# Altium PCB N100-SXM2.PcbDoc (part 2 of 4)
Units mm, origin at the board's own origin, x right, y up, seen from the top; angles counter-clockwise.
Board outline 120 x 145 mm, 4 copper layers (Top Layer, GND, PWR, Bottom Layer), stack 0.603 mm thick; 267 components, 207 nets, 1440 pads, 915 vias.
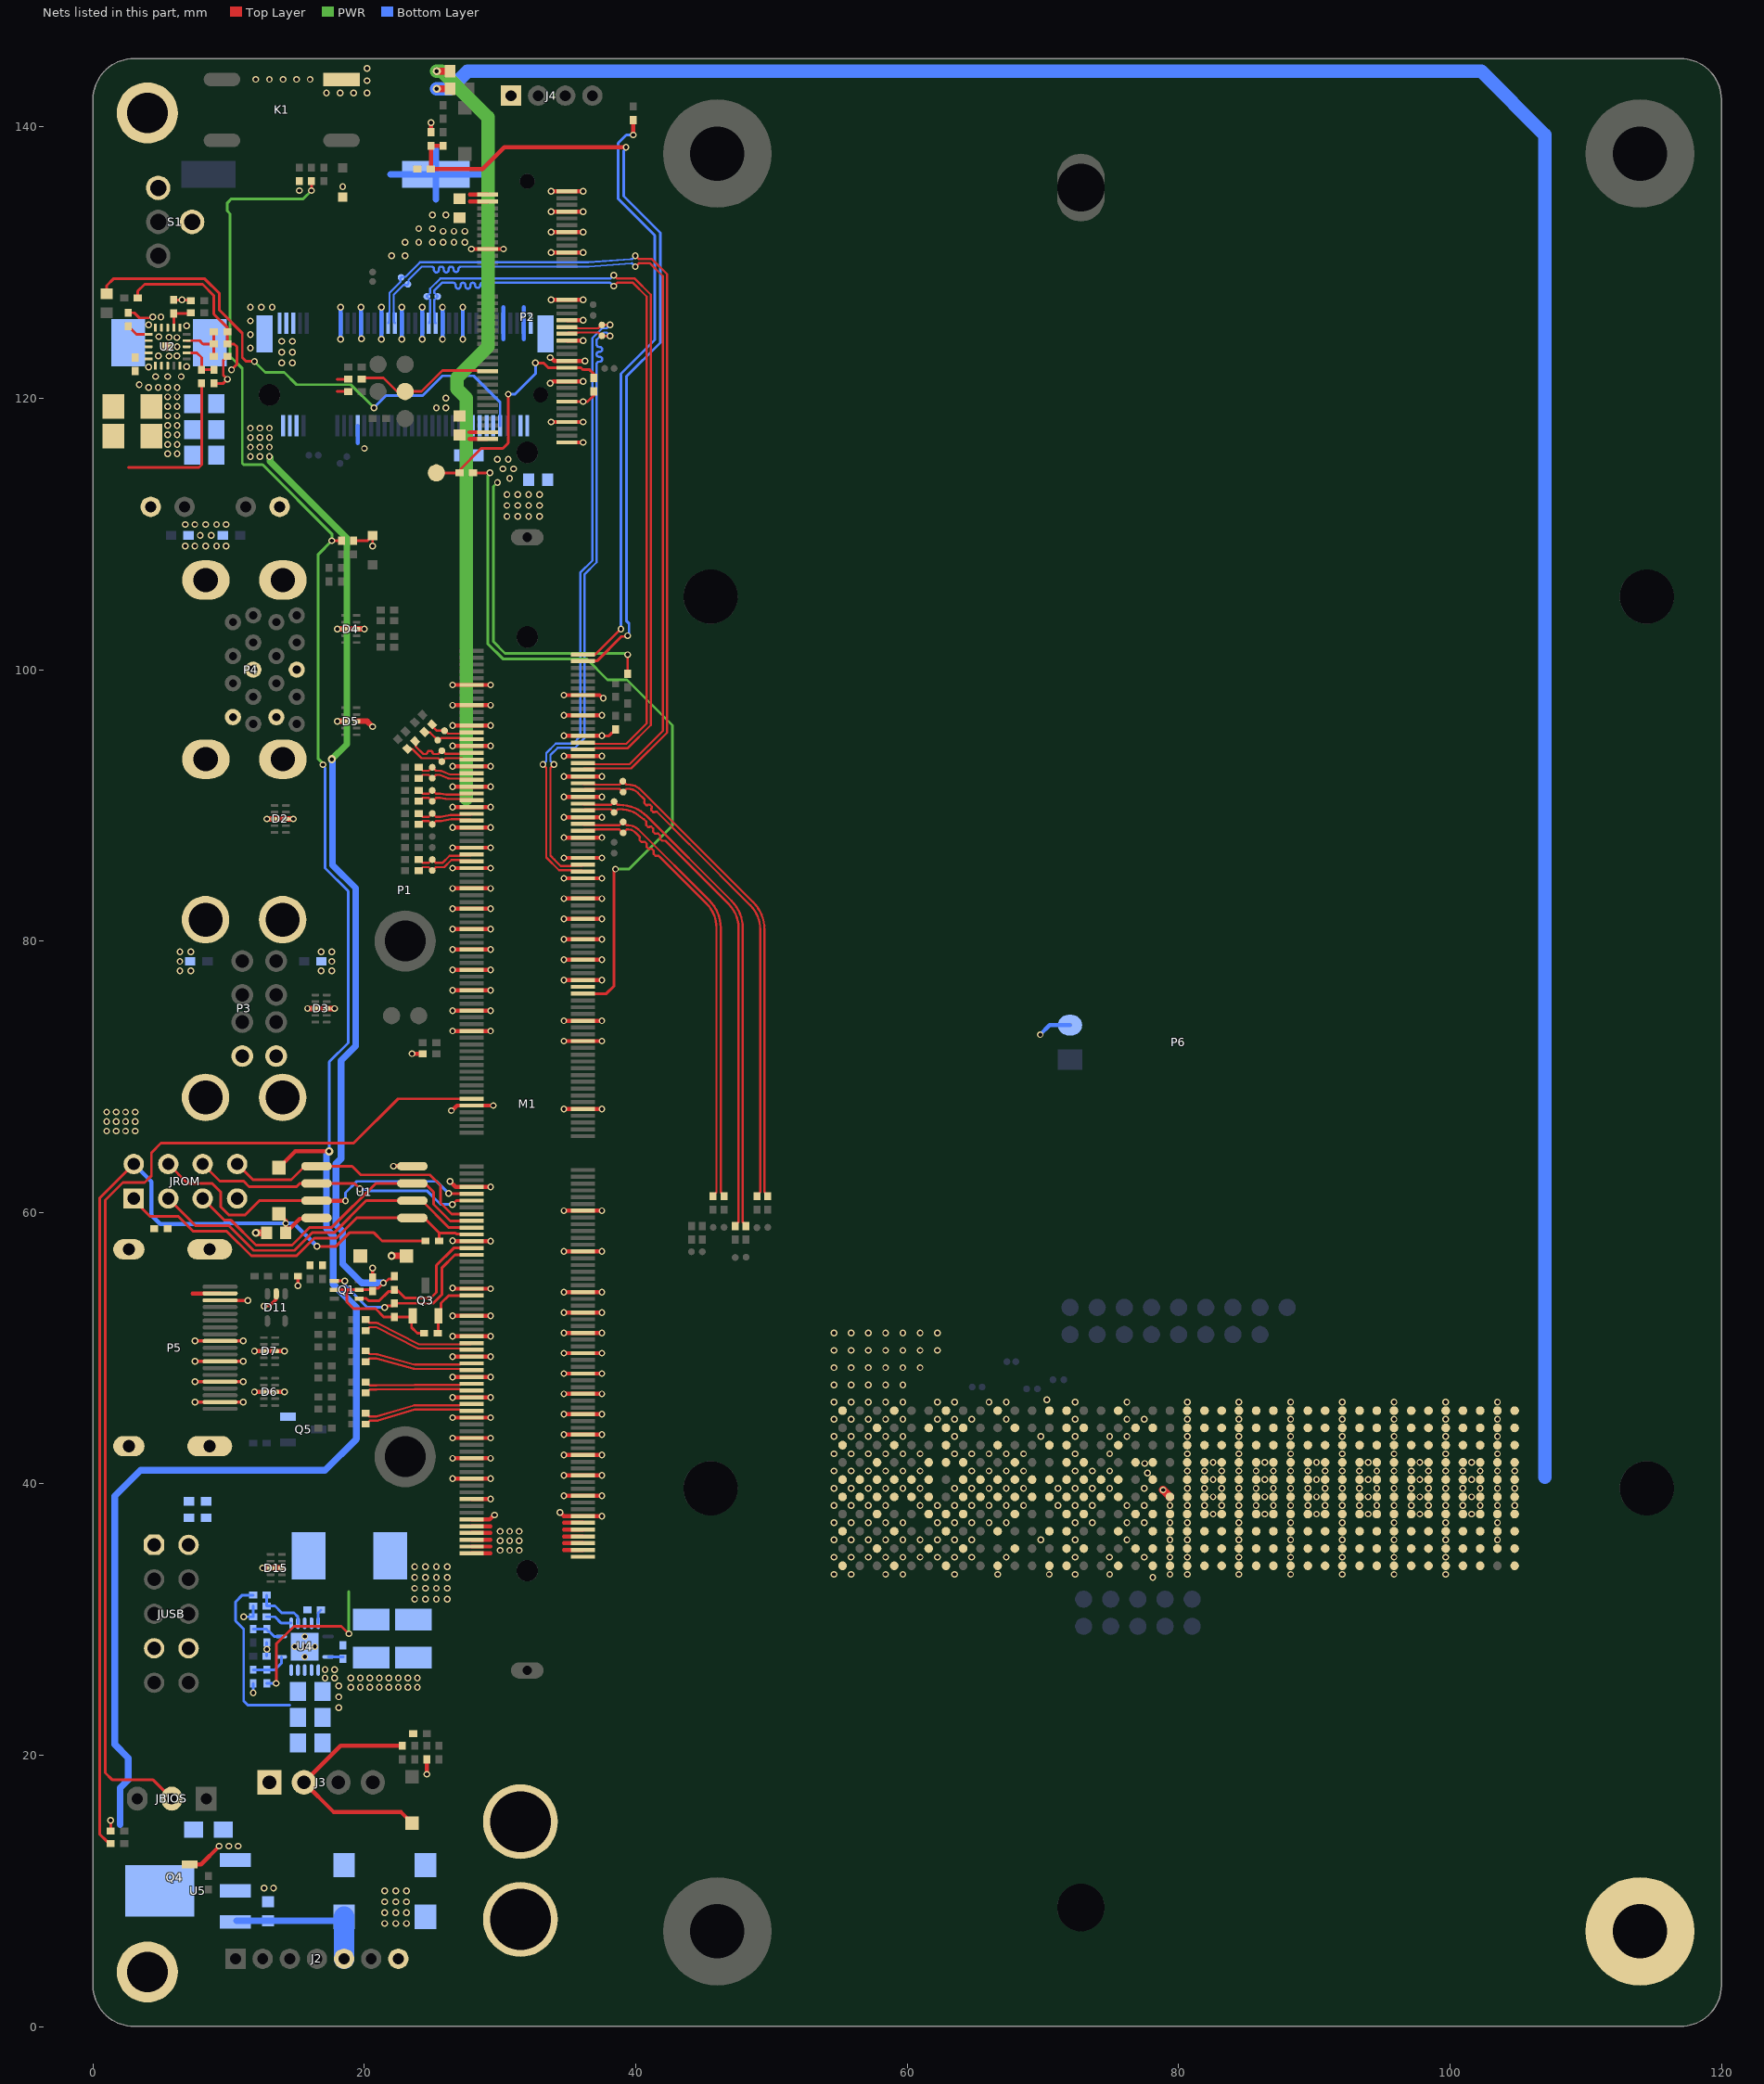
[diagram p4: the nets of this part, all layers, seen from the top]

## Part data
C1 C2 C7 C9 C10 C22 C59 C66: library part C1608-0603, "C1608-0603"
C3 C4 C5 C6 C8 C11 C12 C14 C15 C17 C18 C23 C24 C25 C26 C27 C28 C29 C30 C31 C32 C33 C34 C35 C36 C37 C38 C39 C40 C41 C42 C43 C44 C45 C46 C47 C48 C49 C54 C56 C57 C62 C63 C64 C65 C67 C68: library part C1005-0402, "C1005-0402"
C13 C16: library part CAPPR, "Aluminum Capacitor"
C19 C20 C21 C50 C51 C52: library part C2012-0805, "C2012-0805"
C53 C55: library part C3225-1210, "C3225-1210"
C58: library part TC3216-1206, "Tantalum Capacitor"
C60 C61: library part C3216-1206, "C3216-1206"
D1 D8 D9 D10 D12 D13: library part "Schottky Diode"
D2 D3 D4 D5 D6 D7 D15: library part TPD4E05U06
D14: library part LED0603-B
D16 D17: library part "TVS Diode"
F1 F2 F3 F4 F5 F6: library part FU, "贴片保险丝"
J1 NTC: library part "Pin HDR1X2"
L1 L2: library part INDUCTOR, "INDUCTOR"
M1: "A micro computing module with x86 processer, RAM and eMMC."
P1: "Socket 3 PCIe-based Module"
P2: "Socket 1 PCIe-based Module"
P6: library part SXM2-PCIEonly
Q3 Q4 Q5: library part AO3400A, "N-Channel MOSFET"
R1 R2 R3 R4 R7 R8 R9 R10 R11 R12 R13 R16 R17 R18 R19 R20 R21 R22 R30 R33 R34 R35 R36 R37 R38 R39 R40 R46 R47 R48 R49 R50 R57 R59: library part R1608-0603, "Resistor"
R5 R6 R14 R15 R23 R24 R25 R26 R27 R28 R29 R31 R32 R41 R42 R43 R44 R45 R51 R52 R53 R54 R55 R56 R58: library part R1005-0402, "Resistor"
S1: "https://item.taobao.com/item.htm?id=677075017698"
TP1 TP2 TP3 TP4 TP5 TP6 TP7 TP8 TP9 TP10 TP11 TP12 TP13 TP14 TP15 TP16 TP17 TP18 TP19 TP20 TP21 TP22 TP23 TP24 TP25 TP26 TP27 TP28 TP29 TP30 TP31 TP32 TP66 TP67 TP68 TP69 TP70 TP71 TP72 TP73 TP74 TP75 TP76 TP77 TP78 TP79 TP80 TP81 TP82 TP83 TP84 TP85 TP86 TP87: library part TestPoint_HS
U1: library part GD25Q40CTIG
U2: library part TPS568230
U4: library part TPS54821
U5: library part AMS1117, "三端稳压芯片"

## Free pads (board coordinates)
  round 4.5 hole 3 paste-2539.97 mask+0: 0(4,4.025) 0(4,141.025)

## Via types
v1: diameter 0.5, hole 0.3, Top Layer to Bottom Layer, tented both sides, 908 vias
v2: diameter 0.6, hole 0.3, Top Layer to Bottom Layer, tented both sides, 6 vias
v3: diameter 1.5, hole 1.5, Top Layer to Bottom Layer, tented both sides, 1 vias

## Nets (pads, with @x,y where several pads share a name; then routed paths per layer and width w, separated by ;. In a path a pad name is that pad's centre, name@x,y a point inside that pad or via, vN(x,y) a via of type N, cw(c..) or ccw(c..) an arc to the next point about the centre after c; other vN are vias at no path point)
3V3_BST: C12.2 U2.1 | length 1.7
  Top Layer w0.2: C12.2@2.6,125.3 3.2,124.7 U2.1@4.1,124.7
3V3_EN: R10.1 R13.2 U2.12 | length 3
  Top Layer w0.2: U2.12@6.9,123.35 7.65,123.35 8,123 R10.1@8,122.1 R13.2@8.9,122.1
3V3_FB: C23.1 R11.1 R39.2 U2.14 | length 3.9
  Top Layer w0.2: U2.14@6.9,124.25 7.85,124.25 8.1,124 R11.1@8.9,124 ; R39.2@8.9,123.1 C23.1@8.9,124.9
3V3_SW: C12.1 L2.1 U2.6 U2.19 U2.20 | length 1.6
  Top Layer w0.2: C12.1@2.6,126.3 3.043,126.3 3.418,125.924 4.076,125.924
  other v1: 4.6,121.6 4.1,122.3 4.821,123.117 4.838,124.542 4.1,125.4 4.4,126 5,126
3V3_VCC: C24.2 R12.2 U2.17 | length 2.3
  Top Layer w0.2: U2.17@5.95,125.2 C24.2@5.95,126.25 R12.2@7.15,126.25
5V_BST: C25.2 U4.13 | length 1.1
  Bottom Layer w0.2: U4.13@16.6,29.725 16.6,30.5 C25.2@16.8,30.7
5V_COMP: C57.2 R37.1 U4.8 | length 2.3
  Bottom Layer w0.2: R37.1@11.8,29.3 C57.2@12.8,29.3 12.8,29.254 12.954,29.1 13,29.1 13.35,28.75 U4.8@13.875,28.75
5V_EN: R33.2 R35.1 U4.10 | length 3.9
  Bottom Layer w0.2: R33.2@12.8,31.8 R35.1@12.8,31 13.4,31 13.9,30.5 14.8,30.5 15.1,30.2 U4.10@15.1,29.725
5V_HDMI: C11.1 D10.1 P5.18 R27.2 R28.2 | length 2
  Top Layer w0.3: 7.325,54.025 P5.18@9.36,54.025
5V_RT: R36.1 U4.1 | length 1.1
  Bottom Layer w0.2: U4.1@17.325,27.25 R36.1@18.45,27.25
5V_SS: C54.2 U4.9 | length 2
  Bottom Layer w0.2: C54.2@12.8,30.2 13.4,30.2 13.875,29.725 U4.9@14.6,29.725
5V_SW: C25.1 L1.1 U4.11 U4.12
5V_VFB: R34.1 R38.2 U4.7 | length 2.7
  Bottom Layer w0.2: R38.2@11.8,26.3 R34.1@12.8,26.3 12.9,26.3 13.4,26.3 13.875,26.775 U4.7@13.875,27.25
+3V3: C1.2 C2.2 C7.2 C19.2 C20.2 C21.2 C23.2 C65.1 C66.2 L2.2 P1.2 P1.4 P1.12 P1.14 P1.16 P1.18 P1.70 P1.72 P1.74 P2.2 P2.4 P2.72 P2.74 Q1.2 Q1.5 Q3.1 R11.2 R16.1 R24.2 R25.2 R26.2 R42.1 R43.1 R44.1 | length 124
  Top Layer w0.2: R44.1@3.3,127.4 3.3,127.9 3.8,128.4 8.069,128.4 8.9,127.569 8.9,126.2 9.9,125.2 C23.2@9.9,124.9 R11.2@9.9,124 10.4,124 10.6,123.8 10.6,122.5 v1(10.2,122.1) ; Q1.2@17.78,54.3 18.7,54.3 ; 18,120.5 R43.1@18.8,120.5 ; 18,121.4 R42.1@18.8,121.4 ; C65.1@20.5,54.3 Q1.5@19.62,54.3 18.7,54.3 ; C65.1@20.6,54.2 20.6,54.246 20.754,54.4 21,54.4 v1(21.4,54.8) 21.481,54.8 21.781,55.1 22.046,55.1 22.2,55.254 R25.2@22.2,55.3 ; R26.2@24.4,51.1 23.9,51.1 23.475,51.525 23.475,52.3 R24.2@22.2,52.3 21.422,52.3 20.822,52.9 19.2,52.9 18.7,53.4 18.7,54.3 ; R16.1@39.4,99.7 v1(39.4,101.1)
  Top Layer w0.3: 27.745,117 P2.74@29.055,117 ; 27.745,117.5 P2.72@29.055,117.5 ; 27.76,134.5 P2.4@29.07,134.5 ; 27.76,135 P2.2@29.07,135
  PWR w0.2: v1(29.806,113.8) 29.5,113.494 29.5,102.066 30.366,101.2 39.3,101.2 v1(39.4,101.1)
  PWR w0.5: v1(13,115.7) 13.05,115.65 13.05,115.357 13.05,115.35 18.7,109.7 18.7,94.5 v2(17.6,93.4)
  Bottom Layer w0.5: v2(17.6,93.4) 17.619,93.381 17.619,93.226 17.65,93.195 17.65,85.607 19.35,83.907 19.35,72.272 18.274,71.196 18.274,63.965 17.9,63.591 17.9,59.094 18.4,58.594 18.4,56.2 19.8,54.8 v1(21.4,54.8)
  other v1: 30.5,111.3 31.3,111.3 32.1,111.3 32.9,111.3 30.5,112.1 31.3,112.1 32.1,112.1 32.9,112.1 30.5,112.9 31.3,112.9 32.1,112.9 32.9,112.9 11.6,115.7 12.3,115.7 11.6,116.4 12.3,116.4 13,116.4 11.6,117.1 12.3,117.1 13,117.1 11.6,117.8 12.3,117.8 13,117.8
+3V3_ROM: C22.2 D1.1 JROM.2 R2.2 R4.1 U1.8 | length 81.9
  Top Layer w0.2: R2.2@1.3,13.5 1.146,13.654 1.017,13.654 0.5,14.171 0.5,61.066 2.034,62.6 JROM.2@3,63.565 ; v1(16.5,57.5) 17.9,57.5 18.9,58.5 20.7,58.5 21.3,57.9 R4.1@24.5,57.9
  Top Layer w0.3: D1.1@13.7,59.9 14.2,59.4 v1(14.2,59.2) C22.2@14.2,58.55 ; C22.2@14.225,58.525 15.237,59.537 16.412,59.537 U1.8@16.47,59.595
  Bottom Layer w0.3: JROM.2@3,63.565 4.3,62.265 4.3,59.8 4.95,59.15 9.623,59.15 9.673,59.2 14.8,59.2 v1(16.5,57.5)
+3V3_SB: C58.1 D1.2 R46.1 R50.1 U5.2 | length 154.6
  Top Layer w0.2: v1(16.1,135.3) R50.1@16.1,136 ; v1(17.6,109.5) R46.1@18.3,109.5
  Top Layer w0.3: D1.2@13.7,63.3 14.05,63.65 14.9,64.5 v2(17.4,64.5)
  PWR w0.2: v1(16.1,135.3) 15.5,134.7 10.2,134.7 9.9,134.4 9.9,133.8 10.1,133.6 10.1,123.1 11,122.2 11,115.2 11.1,115.1 12.5,115.1 17.6,110 v1(17.6,109.5) 16.6,108.5 16.6,93.424 16.95,93.074 v1(16.95,92.992)
  Bottom Layer w0.2: v1(16.95,92.992) 16.95,92.911 17.1,92.761 17.1,85.379 18.8,83.679 18.8,72.5 17.4,71.1 v2(17.4,64.5)
  Bottom Layer w0.5: 2,14.9 2,17.6 2.6,18.2 2.6,19.8 1.6,20.8 1.6,39.1 3.5,41 17.1,41 19.4,43.3 19.4,53 17.7,54.7 17.7,58.3 17.2,58.8 17.2,64.273 17.4,64.473 v2(17.4,64.5)
+5V: C53.2 C55.2 D10.2 F1.1 F2.1 F3.1 F4.1 F5.1 F6.1 L1.2 P6.F20 P6.G20 P6.H20 P6.J20 P6.K20 R19.1 R34.2 | length 72.2
  Top Layer w0.2: v1(13.5,25.3) 13.5,28.2 14.8,29.5 18.3,29.5 v1(18.85,28.95)
  Top Layer w0.5: v2(22,56.8) D10.2@23.1,56.8 ; v2(25.327,144.1) R19.1@26.3,144.1
  Top Layer w0.6: v1(78.857,39.548) P6.F20@79.365,39.04
  PWR w0.2: v1(18.85,28.95) 18.85,32.05
  PWR w1: v2(25.327,144.1) 25.7,144.1 29.1,140.7 29.1,123.8 26.814,121.514 26.814,120.686 27.5,120 27.5,100.1 27.5,90.5
  Bottom Layer w0.2: R34.2@12.8,25.3 v1(13.5,25.3)
  other v1: 23.7,31.5 24.5,31.5 25.3,31.5 26.1,31.5 23.7,32.3 24.5,32.3 25.3,32.3 26.1,32.3 23.7,33.1 24.5,33.1 25.3,33.1 26.1,33.1 79.365,33.325 23.7,33.9 24.5,33.9 25.3,33.9 26.1,33.9 79.365,34.595 79.365,35.865 79.365,37.135 79.365,38.405 6.4,77.8 7.2,77.8 16.8,77.8 17.6,77.8 6.4,78.5 17.6,78.5 6.4,79.2 7.2,79.2 16.8,79.2 17.6,79.2 6.8,109.1 7.5,109.1 8.3,109.1 9.1,109.1 9.8,109.1 7.9,109.9 8.7,109.9 6.8,110.7 7.5,110.7 8.3,110.7 9.1,110.7 9.8,110.7
+12V_CPU: D12.1 D13.1 M1.250 M1.251 M1.252 M1.253 M1.254 M1.255 M1.256 M1.257 M1.258 M1.259 M1.260 | length 14
  Top Layer w0.3: M1.259@27.9,34.875 29.3,34.875 ; M1.257@27.9,35.375 29.3,35.375 ; M1.255@27.9,35.875 29.3,35.875 ; M1.253@27.9,36.375 29.3,36.375 ; M1.251@27.9,36.875 29.3,36.875 ; 34.7,35.125 M1.258@36.1,35.125 ; 34.7,35.625 M1.256@36.1,35.625 ; 34.7,36.125 M1.254@36.1,36.125 ; 34.7,36.625 M1.252@36.1,36.625 ; 34.7,37.125 M1.250@36.1,37.125
  other v1: 30,35.1 30.7,35.1 31.4,35.1 30,35.8 30.7,35.8 31.4,35.8 30,36.5 30.7,36.5 31.4,36.5
+12V_IN: C50.2 C51.2 C52.2 C60.2 C61.2 C62.2 D8.1 D13.2 J1.1 J3.2 P6.A22 P6.A23 P6.A25 P6.A26 P6.A28 P6.A29 P6.A31 P6.A32 P6.A34 P6.A35 P6.A37 P6.A38 P6.A40 P6.B22 P6.B23 P6.B25 P6.B26 P6.B28 P6.B29 P6.B31 P6.B32 P6.B34 P6.B35 P6.B37 P6.B38 P6.B40 P6.C22 P6.C23 P6.C25 P6.C26 P6.C28 P6.C29 P6.C31 P6.C32 P6.C34 P6.C35 P6.C37 P6.C38 P6.C40 P6.D22 P6.D23 P6.D25 P6.D26 P6.D28 P6.D29 P6.D31 P6.D32 P6.D34 P6.D35 P6.D37 P6.D38 P6.D40 P6.E22 P6.E23 P6.E25 P6.E26 P6.E28 P6.E29 P6.E31 P6.E32 P6.E34 P6.E35 P6.E37 P6.E38 P6.E40 P6.F22 P6.F23 P6.F25 P6.F26 P6.F28 P6.F29 P6.F31 P6.F32 P6.F34 P6.F35 P6.F37 P6.F38 P6.F40 P6.G22 P6.G23 P6.G25 P6.G26 P6.G28 P6.G29 P6.G31 P6.G32 P6.G34 P6.G35 P6.G37 P6.G38 P6.G40 P6.H22 P6.H23 P6.H25 P6.H26 P6.H28 P6.H29 P6.H31 P6.H32 P6.H34 P6.H35 P6.H37 P6.H38 P6.H40 P6.J22 P6.J23 P6.J25 P6.J26 P6.J28 P6.J29 P6.J31 P6.J32 P6.J34 P6.J35 P6.J37 P6.J38 P6.J40 P6.K22 P6.K23 P6.K25 P6.K26 P6.K28 P6.K29 P6.K31 P6.K32 P6.K34 P6.K35 P6.K37 P6.K38 P6.K40 R7.1 R10.2 R18.1 R33.1 U2.2 U2.3 U2.4 U2.5 U4.4 U4.5 U4.6 | length 225.7
  Top Layer w0.2: 2.6,114.9 7.8,114.9 8,115.1 R10.2@8,121.1
  Top Layer w0.3: R7.1@22.8,20.7 18.24,20.7 J3.2@15.54,18 17.74,15.8 22.7,15.8 D8.1@23.5,15
  Top Layer w0.5: v2(25.327,142.8) R18.1@26.3,142.8
  Bottom Layer w0.2: R33.1@11.8,31.8 11,31.8 10.5,31.3 10.5,29.9 11.1,29.3 11.1,24 11.4,23.7 14.5,23.7
  Bottom Layer w1: v2(25.327,142.8) 26.3,142.8 27.6,144.1 102.3,144.1 107,139.4 107,40.5
  other v1: 21.5,7.6 22.3,7.6 23.1,7.6 21.5,8.4 22.3,8.4 23.1,8.4 21.5,9.2 22.3,9.2 23.1,9.2 21.5,10 22.3,10 23.1,10 82.54,37.77 86.35,37.77 90.16,37.77 93.97,37.77 97.78,37.77 101.59,37.77 81.905,38.405 83.175,38.405 85.715,38.405 86.985,38.405 89.525,38.405 90.795,38.405 93.335,38.405 94.605,38.405 97.145,38.405 98.415,38.405 100.955,38.405 102.225,38.405 104.765,38.405 82.54,39.04 86.35,39.04 90.16,39.04 93.97,39.04 97.78,39.04 101.59,39.04 81.905,39.675 83.175,39.675 85.715,39.675 86.985,39.675 89.525,39.675 90.795,39.675 93.335,39.675 94.605,39.675 97.145,39.675 98.415,39.675 100.955,39.675 102.225,39.675 104.765,39.675 82.54,40.31 86.35,40.31 90.16,40.31 93.97,40.31 97.78,40.31 101.59,40.31 81.905,40.945 83.175,40.945 85.715,40.945 86.985,40.945 89.525,40.945 90.795,40.945 93.335,40.945 94.605,40.945 97.145,40.945 98.415,40.945 100.955,40.945 102.225,40.945 104.765,40.945 82.54,41.58 86.35,41.58 90.16,41.58 93.97,41.58 97.78,41.58 101.59,41.58 1,66 1.7,66 2.4,66 3.1,66 1,66.7 1.7,66.7 2.4,66.7 3.1,66.7 1,67.4 1.7,67.4 2.4,67.4 3.1,67.4
+12VSB: C59.2 D12.2 J2.5 U5.3 | length 10.7
  Bottom Layer w0.5: U5.3@10.586,7.8 C59.2@12.9,7.8 D12.2@18.2,7.8
  Bottom Layer w1.5: J2.5@18.5,5 D12.2@18.5,8.1
BIOS_CLK: JROM.6 M1.155 U1.6 | length 21.4
  Top Layer w0.2: JROM.6@8.08,63.565 9.345,62.3 11.1,62.3 11.5,61.9 15,61.9 15.235,62.135 U1.6@16.47,62.135 19.265,62.135 v1(19.661,61.739) ; v1(26.489,60.589) 26.775,60.875 M1.155@27.9,60.875
  Bottom Layer w0.2: v1(19.661,61.739) 19.7,61.7 20.211,61.7 20.311,61.6 24.6,61.6 25.611,60.589 v1(26.489,60.589)
BIOS_CS: JROM.1 M1.165 R4.2 U1.1 | length 28.9
  Top Layer w0.2: JROM.1@3,61.025 3,60.925 4.225,59.7 6.3,59.7 7.375,58.625 9.844,58.625 11.669,56.8 15,56.8 16.3,58.1 17.931,58.1 19.426,59.595 24.405,59.595 25.525,58.475 26.715,58.475 26.765,58.425 27.85,58.425 M1.165@27.9,58.375 ; R4.2@25.5,57.9 25.5,58.45
BIOS_D0: JROM.8 M1.159 U1.5 | length 20.7
  Top Layer w0.2: JROM.8@10.927,63.565 JROM.8@10.62,63.565 11.785,62.4 14.6,62.4 15.605,63.405 U1.5@16.47,63.405 19.095,63.405 19.73,62.77 24.83,62.77 25.6,62 25.6,60.7 26.425,59.875 M1.159@27.9,59.875
BIOS_D1: JROM.3 M1.163 U1.2 | length 26.3
  Top Layer w0.2: JROM.3@5.54,61.025 6.465,60.1 7.541,59.025 10.009,59.025 11.834,57.2 14.834,57.2 16.134,58.5 17.766,58.5 20.131,60.865 24.235,60.865 26.225,58.875 M1.163@27.9,58.875
BIOS_D2: JROM.5 M1.161 U1.3 | length 24.8
  Top Layer w0.2: JROM.5@8.08,61.025 9.68,59.425 10.175,59.425 12,57.6 14.669,57.6 15.969,58.9 17.6,58.9 20.835,62.135 24.456,62.135 24.629,61.963 24.637,61.963 25.1,61.5 25.1,60.6 26.325,59.375 M1.161@27.9,59.375
BIOS_D3: JROM.4 M1.153 U1.7 | length 26.3
  Top Layer w0.2: JROM.4@5.54,63.565 6.98,62.125 8.8,62.125 9.4,61.525 9.4,60.425 10,59.825 11.225,59.825 12.265,60.865 U1.7@16.47,60.865 ; v1(26.2,61.4) 26.225,61.375 M1.153@27.9,61.375
  Top Layer w0.3: U1.7@16.47,60.865 v1(18.6,60.865)
  Bottom Layer w0.2: v1(18.6,60.865) 18.6,61.456 19.433,62.289 25.311,62.289 v1(26.2,61.4)
BIOS_SEL: JBIOS.2 M1.133 | length 79
  Top Layer w0.2: JBIOS.2@5.8,16.8 4.4,18.2 1.4,18.2 0.9,18.7 0.9,60.9 2.2,62.2 3.8,62.2 4.3,62.7 4.3,64.4 5,65.1 19.2,65.1 22.475,68.375 M1.133@27.9,68.375
BT_OFF: P2.54 R42.2 TP62.1 | length 10.3
  Top Layer w0.2: R42.2@19.8,121.5 21.4,121.5 22.4,120.5 TP62.1@23,120.5 24.2,120.5 25.75,122.05 29.02,122.05 P2.54@29.07,122
CLKREQ3: M1.100
CLKREQ4: M1.102 R5.2 | length 54.2
  Top Layer w0.2: R5.2@28,114.5 29.266,114.5 v1(29.25,114.516) ; M1.102@36.1,76.125 37.825,76.125 38.4,76.7 38.4,85.206 v1(38.497,85.302)
  PWR w0.2: v1(29.25,114.516) 29.1,114.366 29.1,101.9 30.2,100.8 36.366,100.8 37.916,99.25 39.35,99.25 42.7,95.9 42.7,88.5 39.502,85.302 v1(38.497,85.302)
CLKREQ_E: P2.53 R5.1 R6.1 TP64.1 | length 18.3
  Top Layer w0.2: TP64.1@25.3,114.5 R5.1@27,114.5 27,114.7 28.6,116.3 30.2,116.3 30.6,116.7 v1(30.6,120.3) ; v1(32.6,122.6) 33.2,122.6 33.55,122.25 P2.53@34.93,122.25 35.972,122.25 36.122,122.1 36.6,122.1 36.9,121.8 R6.1@36.9,121.5
  Bottom Layer w0.2: v1(30.6,120.3) 31.1,120.3 32.6,121.8 v1(32.6,122.6)
CPU_FAN_PWM: M1.2 R22.2 | length 43.8
  Top Layer w0.2: M1.2@36.1,101.125 37.025,101.125 v1(38.9,103)
  Top Layer w0.3: v1(39.8,139.4) R22.2@39.8,140.3
  Bottom Layer w0.2: v1(38.9,103) 38.9,121.8 41.4,124.3 41.4,132 38.7,134.7 38.7,138.8 39.3,139.4 v1(39.8,139.4)
CPU_FAN_TAC: C10.2 M1.4 R21.2 R59.1 | length 60.1
  Top Layer w0.2: M1.4@36.1,100.625 36.112,100.637 37.137,100.637 38.943,102.443 39.343,102.443 v1(39.4,102.5)
  Top Layer w0.3: R21.2@25.8,138.6 C10.2@24.9,138.6 R59.1@24.9,136.9 28.7,136.9 30.3,138.5 v1(39.278,138.5)
  Bottom Layer w0.2: v1(39.278,138.5) 39.278,138.419 39.1,138.24 39.1,134.9 41.8,132.2 41.8,124.1 39.3,121.6 39.3,103.6 39.5,103.4 39.5,102.6 v1(39.4,102.5)
DAS#: D14.1 P1.10 | length 39
  Top Layer w0.2: D14.1@1,127.7 1,128.3 1.5,128.8 8.234,128.8 9.3,127.734 9.3,126.5 11,124.8 11,123 11.261,122.739 11.861,122.739 v1(11.9,122.7)
  PWR w0.2: v1(11.9,122.7) 12.7,121.9 14.1,121.9 15,121 19,121 v1(20.7,119.3)
  Bottom Layer w0.2: v1(20.7,119.3) 21.6,120.2 24.3,120.2 25.75,121.65 28.05,121.65 30,119.7 P1.10@30,117.975
DDI_B_HPD: M1.183 Q3.2 R26.1 | length 4.8
  Top Layer w0.2: R26.1@25.45,51.1 Q3.2@25.45,52.375 25.65,52.575 25.65,53.319 26.206,53.875 M1.183@27.9,53.875
DDI_B_SCL: M1.171 Q1.1 R24.1 | length 13.9
  Top Layer w0.2: Q1.1@17.78,54.95 v1(18.55,54.95) ; v1(21.5,53) 21.581,53 21.681,53.1 22.046,53.1 22.2,53.254 R24.1@22.2,53.3 25.066,53.3 25.7,53.934 25.7,55.9 26.675,56.875 M1.171@27.9,56.875
  Bottom Layer w0.2: v1(18.55,54.95) 18.55,54.65 20.2,53 v1(21.5,53)
DDI_B_SDA: M1.169 Q1.4 R25.1 | length 11.6
  Top Layer w0.2: Q1.4@19.62,53.65 20.15,53.65 20.3,53.5 21.1,53.5 21.763,54.163 22.063,54.163 R25.1@22.2,54.3 22.4,54.3 23,53.7 24.9,53.7 25.3,54.1 25.3,56.1 26.575,57.375 M1.169@27.9,57.375
DDI_B_TX0_N: C27.2 M1.215 | length 8.1
  Top Layer w0.161: C27.2@20.096,45.2 20.142,45.2 20.386,44.956 20.878,44.956 23.615,45.767 cw(c23.705,45.47) 23.705,45.781 27.011,45.781 27.036,45.806 27.831,45.806 M1.215@27.9,45.875
DDI_B_TX0_P: C26.2 M1.217 | length 8.1
  Top Layer w0.161: C26.2@20.096,44.4 20.142,44.4 20.386,44.645 20.878,44.645 ccw(c20.878,44.956) 20.879,44.645 ; 20.88,44.645 ccw(c20.878,44.956) 20.967,44.658 23.705,45.47 27.011,45.47 27.036,45.445 27.831,45.445 M1.217@27.9,45.375
DDI_B_TX1_N: C29.2 M1.209 | length 7.9
  Top Layer w0.161: C29.2@20.096,47.5 20.142,47.5 20.386,47.256 20.878,47.256 23.701,47.281 cw(c23.705,46.97) 23.705,47.281 ; 23.702,47.281 cw(c23.705,46.97) 23.705,47.281 ; M1.209@27.9,47.375 27.831,47.306 27.036,47.306 27.011,47.281 23.705,47.281
DDI_B_TX1_P: C28.2 M1.211 | length 7.9
  Top Layer w0.161: C28.2@20.096,46.7 20.142,46.7 20.386,46.945 20.878,46.945 ccw(c20.878,47.256) 20.883,46.945 23.705,46.97 27.011,46.97 27.036,46.945 27.831,46.945 M1.211@27.9,46.875
DDI_B_TX2_N: C31.2 M1.203 | length 8.1
  Top Layer w0.161: C31.2@20.096,49.8 20.142,49.8 20.386,49.555 20.878,49.555 cw(c20.878,49.244) 20.963,49.544 23.705,48.781 27.011,48.781 27.036,48.806 27.831,48.806 M1.203@27.9,48.875
DDI_B_TX2_P: C30.2 M1.205 | length 8.1
  Top Layer w0.161: C30.2@20.096,49 20.142,49 20.386,49.244 20.878,49.244 23.621,48.481 ccw(c23.705,48.781) 23.623,48.481 ccw(c23.705,48.781) 23.704,48.47 ccw(c23.705,48.781) 23.705,48.47 27.011,48.47 27.036,48.445 27.831,48.445 M1.205@27.9,48.375
DDI_B_TX3_N: C33.2 M1.197 | length 8.3
  Top Layer w0.161: C33.2@20.096,52.1 20.142,52.1 20.386,51.855 20.878,51.855 cw(c20.878,51.544) 21.021,51.821 24.029,50.281 27.011,50.281 27.036,50.306 27.831,50.306 M1.197@27.9,50.375
DDI_B_TX3_P: C32.2 M1.199 | length 8.3
  Top Layer w0.161: C32.2@20.096,51.3 20.142,51.3 20.386,51.544 20.878,51.544 23.886,50.004 ccw(c24.029,50.281) 24.029,49.97 27.011,49.97 27.036,49.945 27.831,49.945 M1.199@27.9,49.875
FUSB_VBUS1: F3.2 JUSB.2
FUSB_VBUS2: F4.2 JUSB.1
GND: BAT1.2 C1.1 C2.1 C7.1 C8.1 C9.1 C10.1 C11.2 C13.2 C16.2 C19.1 C20.1 C21.1 C22.1 C24.1 C50.1 C51.1 C52.1 C53.1 C54.1 C55.1 C56.1 C57.1 C58.2 C59.1 C60.1 C61.1 C62.1 C65.2 C66.1 C67.1 C68.1 D2.3 D2.8 D3.3 D3.8 D4.3 D4.8 D5.3 D5.8 D6.3 D6.8 D7.3 D7.8 D11.2 D15.3 D15.8 D16.2 D17.2 J1.2 J2.7 J3.1 J4.1 JROM.7 JUSB.7 JUSB.8 K1.1 M1.11 M1.14 M1.17 M1.20 M1.23 M1.26 M1.29 M1.32 M1.35 M1.38 M1.41 M1.44 M1.47 M1.50 M1.53 M1.56 M1.59 M1.62 M1.65 M1.68 M1.71 M1.74 M1.77 M1.80 M1.83 M1.86 M1.89 M1.92 M1.95 M1.98 M1.101 M1.107 M1.110 M1.113 M1.116 M1.135 M1.136 M1.151 M1.158 M1.167 M1.170 M1.181 M1.182 M1.188 M1.189 M1.194 M1.195 M1.200 M1.201 M1.206 M1.207 M1.212 M1.213 M1.218 M1.219 M1.224 M1.225 M1.230 M1.231 M1.236 M1.237 M1.242 M1.243 M1.248 M1.249 NTC.2 P1.1 P1.3 P1.9 P1.15 P1.21 P1.27 P1.33 P1.39 P1.45 P1.51 P1.52 P1.57 P1.71 P1.73 P1.75 P1.76 P1.77 P2.1 P2.7 P2.13 P2.18 P2.19 P2.33 P2.39 P2.45 P2.51 P2.57 P2.63 P2.69 P2.75 P3.4 P3.8 P3.9 P3.10 P3.11 P3.12 P4.4 P4.7 P4.13 P4.16 P4.19 P4.20 P4.21 P4.22 P5.2 P5.5 P5.8 P5.11 P5.17 P5.20 P5.21 P5.22 P5.23 P6.@114,7.025 P6.A1 P6.A4 P6.A7 P6.A10 P6.A13 P6.A14 P6.A17 P6.A21 P6.A24 P6.A27 P6.A30 P6.A33 P6.A36 P6.A39 P6.B3 P6.B6 P6.B7 P6.B8 P6.B11 P6.B14 P6.B15 P6.B18 P6.B19 P6.B21 P6.B24 P6.B27 P6.B30 P6.B33 P6.B36 P6.B39 P6.C1 P6.C4 P6.C7 P6.C10 P6.C13 P6.C14 P6.C17 P6.C21 P6.C24 P6.C27 P6.C30 P6.C33 P6.C36 P6.C39 P6.D3 P6.D6 P6.D7 P6.D8 P6.D11 P6.D14 P6.D15 P6.D18 P6.D19 P6.D21 P6.D24 P6.D27 P6.D30 P6.D33 P6.D36 P6.D39 P6.E1 P6.E2 P6.E3 P6.E4 P6.E5 P6.E6 P6.E8 P6.E9 P6.E10 P6.E11 P6.E12 P6.E13 P6.E14 P6.E15 P6.E16 P6.E17 P6.E19 P6.E21 P6.E24 P6.E27 P6.E30 P6.E33 P6.E36 P6.E39 P6.F1 P6.F2 P6.F3 P6.F4 P6.F5 P6.F6 P6.F8 P6.F9 P6.F10 P6.F11 P6.F12 P6.F13 P6.F14 P6.F15 P6.F16 P6.F17 P6.F19 P6.F21 P6.F24 P6.F27 P6.F30 P6.F33 P6.F36 P6.F39 P6.G3 P6.G6 P6.G7 P6.G8 P6.G11 P6.G14 P6.G15 P6.G18 P6.G19 P6.G21 P6.G24 P6.G27 P6.G30 P6.G33 P6.G36 P6.G39 P6.H1 P6.H4 P6.H7 P6.H10 P6.H13 P6.H14 P6.H17 P6.H19 P6.H21 P6.H24 P6.H27 P6.H30 P6.H33 P6.H36 P6.H39 P6.J3 P6.J6 P6.J8 P6.J11 P6.J14 P6.J15 P6.J18 P6.J19 P6.J21 P6.J24 P6.J27 P6.J30 P6.J33 P6.J36 P6.J39 P6.K1 P6.K4 P6.K7 P6.K10 P6.K13 P6.K14 P6.K17 P6.K19 P6.K21 P6.K24 P6.K27 P6.K30 P6.K33 P6.K36 pad.0 Q4.2 Q5.2 R3.2 R6.2 R13.1 R31.1 R35.2 R36.2 R38.1 R39.1 R40.2 R57.2 R58.2 R59.2 S1.1 S1.3 U1.4 U2.7 U2.8 U2.10 U2.13 U2.16 U2.18 U2.21 U4.2 U4.3 U4.15 U5.1 | length 300
  Top Layer w0.2: R3.2@1.3,14.4 v1(1.3,15.2) ; C24.1@5.95,127.25 v1(6.55,127.25) R40.2@7.15,127.25 ; R13.1@8.9,121.1 9.6,121.1 v1(9.9,121.4) 9.6,121.7 9.6,122.8 9.7,122.9 9.7,122.946 9.854,123.1 R39.1@9.9,123.1 ; C68.1@19.2,109.5 20.225,109.5 D17.2@20.6,109.875 v1(20.6,109.1) ; P2.63@34.93,119.75 v1(36.11,119.75) 36.45,119.75 36.9,120.2 R6.2@36.9,120.5 ; v1(37.5,95.125) 38.025,95.125 R58.2@38.5,95.6
  Top Layer w0.25: v1(7.52,46.021) 7.522,46.023 9.358,46.023 P5.2@9.36,46.025 9.362,46.023 11.073,46.023 v1(11.075,46.021) ; v1(7.52,47.525) P5.5@9.36,47.525 v1(11.075,47.525) ; v1(7.52,49.025) P5.8@9.36,49.025 v1(11.075,49.025) ; v1(7.52,50.525) P5.11@9.36,50.525 v1(11.075,50.525) ; P5.17@9.36,53.525 9.37,53.515 11.385,53.515 v1(11.4,53.5) ; v1(12.6,53.1) 12.648,53.148 13.048,53.148 13.471,53.571 13.471,53.971 D11.2@13.5,54 ; v1(15.1,54.6) R31.1@15.1,55.3 ; C65.2@20.6,55.2 v1(20.6,55.9)
  Top Layer w0.3: Q4.2@7.125,11.95 7.95,11.95 v1(9.3,13.3) ; v1(11.9,46.775) D6.8@12.582,46.775 D6.3@13.418,46.775 v1(14.1,46.775) ; v1(14.1,49.775) D7.3@13.418,49.775 ; v1(22.13,63.405) U1.4@23.53,63.405 ; v1(23.5,71.7) C8.1@24.3,71.7 ; v1(24.6,18.6) C9.1@24.6,19.5 ; C10.1@24.9,139.6 v1(24.9,140.3) ; v1(26.3,62.3) 26.725,61.875 v1(29.3,61.875) ; v1(26.4,67.5) 26.454,67.5 26.829,67.875 M1.135@27.9,67.875 v1(29.5,67.875) ; v1(26.493,57.919) 26.548,57.919 26.591,57.875 M1.167@27.9,57.875 v1(29.3,57.875) ; v1(26.5,40.375) M1.237@27.9,40.375 v1(29.3,40.375) ; v1(26.5,41.875) M1.231@27.9,41.875 v1(29.3,41.875) ; v1(26.5,43.375) M1.225@27.9,43.375 v1(29.3,43.375) ; v1(26.5,44.875) M1.219@27.9,44.875 v1(29.3,44.875) ; v1(26.5,46.375) M1.213@27.9,46.375 v1(29.3,46.375) ; v1(26.5,47.875) M1.207@27.9,47.875 v1(29.3,47.875) ; v1(26.5,49.375) M1.201@27.9,49.375 v1(29.3,49.375) ; v1(26.5,50.875) M1.195@27.9,50.875 v1(29.3,50.875) ; v1(26.5,52.375) M1.189@27.9,52.375 v1(29.3,52.375) ; v1(26.5,54.425) 26.554,54.425 26.604,54.375 M1.181@27.9,54.375 v1(29.3,54.375) ; v1(26.5,73.375) M1.113@27.9,73.375 v1(29.3,73.375) ; v1(26.5,74.875) M1.107@27.9,74.875 v1(29.3,74.874) ; v1(26.5,76.375) M1.101@27.9,76.375 29.3,76.375 v1(29.301,76.376) ; v1(26.5,77.875) M1.95@27.9,77.875 v1(29.3,77.875) ; v1(26.5,79.375) M1.89@27.9,79.375 v1(29.3,79.375) ; v1(26.5,80.875) M1.83@27.9,80.875 v1(29.3,80.875) ; v1(26.5,82.375) M1.77@27.9,82.375 v1(29.3,82.375) ; v1(26.5,83.875) M1.71@27.9,83.875 v1(29.3,83.875) ; v1(26.5,85.375) M1.65@27.9,85.375 v1(29.3,85.375) ; v1(26.5,86.875) M1.59@27.9,86.875 v1(29.3,86.875) ; v1(26.5,88.375) M1.53@27.9,88.375 v1(29.3,88.375) ; v1(26.5,89.875) M1.47@27.9,89.875 v1(29.3,89.875) v1@29.332,89.875 ; v1(26.5,91.375) M1.41@27.9,91.375 v1(29.3,91.375) ; v1(26.5,92.875) M1.35@27.9,92.875 v1(29.3,92.875) ; v1(26.5,94.375) M1.29@27.9,94.375 v1(29.3,94.375) ; v1(26.5,95.875) M1.23@27.9,95.875 v1(29.3,95.875) ; v1(26.5,97.375) M1.17@27.9,97.375 v1(29.3,97.375) ; v1(26.5,98.875) M1.11@27.9,98.875 v1(29.3,98.875) ; v1(27.89,131) P2.18@29.07,131 v1(30.25,131) ; M1.249@27.9,37.375 29.225,37.375 29.55,37.7 v1(29.6,37.7) ; M1.243@27.9,38.875 v1(29.3,38.875) ; v1(33.7,121.1) 33.754,121.1 33.904,121.25 P2.57@34.93,121.25 v1(36.11,121.25) ; v1(33.7,123) 33.754,123 34.004,122.75 v1(36.25,122.75) ; v1(33.75,118.25) P2.69@34.93,118.25 v1(36.11,118.25) ; v1(33.75,127.25) P2.33@34.93,127.25 v1(36.11,127.25) ; v1(33.75,130.75) P2.19@34.93,130.75 v1(36.11,130.75) ; v1(33.75,132.25) P2.13@34.93,132.25 v1(36.11,132.25) ; v1(33.75,133.75) P2.7@34.93,133.75 v1(36.11,133.75) ; v1(33.75,135.25) P2.1@34.93,135.25 v1(36.11,135.25) ; v1(34.4,37.9) 34.675,37.625 M1.248@36.1,37.625 v1(37.5,37.625) ; v1(34.7,39.125) M1.242@36.1,39.125 v1(37.5,39.125) ; v1(34.7,40.625) M1.236@36.1,40.625 v1(37.5,40.625) ; v1(34.7,42.125) M1.230@36.1,42.125 v1(37.5,42.125) ; v1(34.7,43.625) M1.224@36.1,43.625 v1(37.5,43.625) ; v1(34.7,45.125) M1.218@36.1,45.125 v1(37.5,45.125) ; v1(34.7,46.625) M1.212@36.1,46.625 v1(37.5,46.625) ; v1(34.7,48.125) M1.206@36.1,48.125 v1(37.5,48.125) ; v1(34.7,49.625) M1.200@36.1,49.625 v1(37.5,49.625) ; v1(34.7,51.125) M1.194@36.1,51.125 v1(37.5,51.125) ; v1(34.7,52.625) M1.188@36.1,52.625 v1(37.5,52.625) ; v1(34.7,54.125) M1.182@36.1,54.125 v1(37.5,54.125) ; v1(34.7,57.125) M1.170@36.1,57.125 v1(37.5,57.125) ; v1(34.7,60.125) M1.158@36.1,60.125 v1(37.5,60.125) ; v1(34.7,67.625) M1.136@36.1,67.625 v1(37.5,67.625) ; v1(34.7,72.625) M1.116@36.1,72.625 v1(37.5,72.625) ; v1(34.7,74.125) M1.110@36.1,74.125 v1(37.5,74.125) ; v1(34.7,77.125) M1.98@36.1,77.125 v1(37.5,77.125) ; v1(34.7,78.625) M1.92@36.1,78.625 v1(37.5,78.625) ; v1(34.7,80.125) M1.86@36.1,80.125 v1(37.5,80.125) ; v1(34.7,81.631) 34.706,81.625 M1.80@36.1,81.625 37.494,81.625 v1(37.5,81.631) ; v1(34.7,83.125) M1.74@36.1,83.125 v1(37.5,83.125) ; v1(34.7,84.625) M1.68@36.1,84.625 v1(37.5,84.625) ; v1(34.7,86.125) M1.62@36.1,86.125 v1(37.5,86.125) ; v1(34.7,87.625) M1.56@36.1,87.625 v1(37.5,87.625) ; v1(34.7,89.125) M1.50@36.1,89.125 v1(37.5,89.125) ; v1(34.7,90.625) M1.44@36.1,90.625 v1(37.5,90.625) ; v1(34.7,92.125) M1.38@36.1,92.125 v1(37.5,92.125) ; v1(34.7,93.625) M1.32@36.1,93.625 v1(37.5,93.625) ; v1(34.7,95.125) M1.26@36.1,95.125 v1(37.5,95.125) ; v1(34.7,96.625) M1.20@36.1,96.625 v1(37.5,96.625) ; v1(34.7,98.125) 37.332,98.125 37.557,97.9 v1(37.6,97.9) ; P2.75@34.93,116.75 v1(36.11,116.75) ; P2.45@34.93,124.25 v1(36.11,124.25) ; P2.39@34.93,125.75 v1(36.11,125.75) ; D7.8@12.582,49.775 v1(11.9,49.775) D7.8@12.582,49.775 ; D7.8@12.582,49.775 D7.3@13.418,49.775 ; D7.8@12.582,49.775 D7.3@13.418,49.775
  Top Layer w0.4: v1(12.5,33.8) D15.3@13.082,33.8 13.5,33.8 13.7,33.8 D15.8@13.918,33.8 ; v1(12.8,89) D2.8@13.382,89 13.8,89 14,89 D2.3@14.218,89 v1(14.75,89) ; v1(15.8,75.025) D3.3@16.382,75.025 16.8,75.025 17,75.025 D3.8@17.218,75.025 v1(17.8,75.025) ; v1(18,96.2) D5.8@18.582,96.2 ; v1(18,103) D4.8@18.582,103 D4.3@19.418,103 v1(20,103) ; D5.3@19.418,96.2 20.2,96.2 v1(20.6,95.8)
  Top Layer w0.5: v2(12,58.5) C22.1@12.8,58.5
  Bottom Layer w0.2: v1(11.1,30.2) C54.1@11.8,30.2 R35.2@11.8,31 ; v1(11.8,24.6) R38.1@11.8,25.3 ; C56.1@12.8,27.3 v1(12.8,27.8) C57.1@12.8,28.3
  Bottom Layer w0.3: v1(18.249,124.349) 18.249,124.44 18.25,124.441 18.25,124.9 P1.57@18.25,125.525 v1(18.25,126.7) ; 19.5,116.7 P1.52@19.5,117.975 ; v1(19.75,126.7) 19.75,126.15 19.75,124.403 v1(19.776,124.376) ; v1(21.25,124.35) v1(21.25,126.7) ; v1(22.75,124.35) v1(22.75,126.7) ; v1(24.25,124.35) v1(24.25,126.7) ; v1(25.75,124.35) v1(25.75,126.7) ; v1(27.25,124.35) v1(27.25,126.7) ; 28.75,124.35 28.75,126.7 ; 30.25,124.35 30.25,126.7 ; 31.75,124.35 31.75,126.7 ; v1(69.8,73.1) 70.5,73.8 NTC.2@72,73.8
  Bottom Layer w0.5: 21.928,136.5 BAT1.2@25.264,136.5 ; 25.264,134.664 BAT1.2@25.264,136.5 ; 25.264,138.336 BAT1.2@25.264,136.5 ; 28.6,136.5 BAT1.2@25.264,136.5
  other v1: 12.6,10.2 13.3,10.2 10,13.3 10.7,13.3 18.1,23.5 18.1,24.3 19,25 19.7,25 20.4,25 21.1,25 21.8,25 22.5,25 23.2,25 23.9,25 18.1,25.1 17.1,25.7 17.8,25.7 19,25.7 19.7,25.7 20.4,25.7 21.1,25.7 21.8,25.7 22.5,25.7 23.2,25.7 23.9,25.7 17.1,26.3 17.8,26.3 15.6,27.25 14.85,28 15.6,28 16.35,28 15.6,28.75 78.1,33.1 54.6,33.325 55.87,33.325 58.41,33.325 59.68,33.325 63.49,33.325 66.665,33.325 70.475,33.325 72.38,33.325 74.92,33.325 80.635,33.325 84.445,33.325 88.255,33.325 92.065,33.325 95.875,33.325 99.685,33.325 54.6,34.595 55.87,34.595 57.14,34.595 58.41,34.595 59.68,34.595 60.95,34.595 62.22,34.595 63.49,34.595 64.76,34.595 67.3,34.595 72.38,34.595 74.914,34.59 77.46,34.595 80.635,34.595 84.445,34.595 88.255,34.595 92.065,34.595 95.875,34.595 99.685,34.595 54.6,35.865 55.87,35.865 57.14,35.865 58.41,35.865 59.68,35.865 60.95,35.865 62.22,35.865 63.49,35.865 64.76,35.865 69.84,35.865 72.38,35.865 76.19,35.865 80.635,35.865 84.445,35.865 88.255,35.865 92.065,35.865 95.875,35.865 99.685,35.865 103.495,35.865 54.6,37.135 55.87,37.135 57.14,37.135 58.41,37.135 59.68,37.135 62.22,37.135 63.49,37.135 64.76,37.135 66.03,37.135 67.3,37.135 72.38,37.135 73.65,37.135 76.19,37.135 77.46,37.135 80.635,37.135 84.445,37.135 88.255,37.135 92.065,37.135 95.875,37.135 99.685,37.135 103.495,37.135 54.6,38.405 55.87,38.405 57.14,38.405 58.41,38.405 60.95,38.405 62.22,38.405 63.49,38.405 64.76,38.405 66.03,38.405 67.3,38.405 68.57,38.405 71.11,38.405 72.38,38.405 73.65,38.405 76.19,38.405 77.46,38.405 80.635,38.405 84.445,38.405 88.255,38.405 92.065,38.405 95.875,38.405 99.685,38.405 103.495,38.405 54.6,39.675 55.87,39.675 57.14,39.675 58.41,39.675 59.68,39.675 60.95,39.675 63.49,39.675 64.76,39.675 66.03,39.675 67.3,39.675 68.57,39.675 71.11,39.675 72.38,39.675 73.65,39.675 74.92,39.675 77.46,39.675 80.635,39.675 84.445,39.675 88.255,39.675 92.065,39.675 95.875,39.675 99.685,39.675 103.495,39.675 77.7,40.8 54.6,40.945 55.87,40.945 57.14,40.945 58.41,40.945 59.68,40.945 60.95,40.945 64.76,40.945 66.03,40.945 67.3,40.945 68.57,40.945 72.38,40.945 73.65,40.945 74.92,40.945 80.635,40.945 84.445,40.945 88.255,40.945 92.065,40.945 95.875,40.945 99.685,40.945 103.495,40.945 77.5,41.5 54.6,42.215 55.87,42.215 57.14,42.215 58.41,42.215 59.68,42.215 60.95,42.215 63.49,42.215 64.76,42.215 66.03,42.215 67.3,42.215 68.57,42.215 72.38,42.215 74.92,42.215 80.635,42.215 84.445,42.215 88.255,42.215 92.065,42.215 95.875,42.215 99.685,42.215 103.495,42.215 54.6,43.485 55.87,43.485 57.14,43.485 58.41,43.485 59.68,43.485 63.49,43.485 69.84,43.485 72.38,43.485 74.92,43.485 76.19,43.485 80.635,43.485 84.445,43.485 88.255,43.485 92.065,43.485 95.875,43.485 99.685,43.485 103.495,43.485 54.6,44.755 55.87,44.755 57.14,44.755 58.41,44.755 59.68,44.755 62.22,44.755 63.49,44.755 64.76,44.755 67.3,44.755 72.38,44.755 76.19,44.755 77.46,44.755 80.635,44.755 84.445,44.755 88.255,44.755 92.065,44.755 95.875,44.755 99.685,44.755 103.495,44.755 54.6,46.025 55.87,46.025 57.14,46.025 58.41,46.025 59.68,46.025 62.22,46.025 63.49,46.025 66.03,46.025 67.3,46.025 72.38,46.025 76.19,46.025 80.635,46.025 84.445,46.025 88.255,46.025 92.065,46.025 95.875,46.025 99.685,46.025 103.495,46.025 70.3,46.2 54.6,47.295 55.87,47.295 57.14,47.295 58.41,47.295 59.68,47.295 54.6,48.565 55.87,48.565 57.14,48.565 58.41,48.565 59.68,48.565 60.95,48.565 54.6,49.835 55.87,49.835 57.14,49.835 58.41,49.835 59.68,49.835 60.95,49.835 62.22,49.835 54.6,51.105 55.87,51.105 57.14,51.105 58.41,51.105 59.68,51.105 60.95,51.105 62.22,51.105 30.7,114.1 30.2,114.8 31,114.8 29.8,115.5 30.6,115.5 5.5,115.9 6.2,115.9 20,116.3 5.5,116.6 6.2,116.6 5.5,117.3 6.2,117.3 5.5,118 6.2,118 5.5,118.7 6.2,118.7 25.3,119.3 26,119.3 5.5,119.4 6.2,119.4 26,120 5.5,120.1 6.2,120.1 4.1,120.8 4.8,120.8 5.5,120.8 6.2,120.8 3.4,121 5.5,121.6 6.5,121.6 6.9,122.325 13.9,122.6 14.7,122.6 5.6,123.1 6.175,123.125 13.9,123.4 14.7,123.4 11.6,123.7 6.2,123.8 13.9,124.2 14.7,124.2 6.175,124.475 5.6,124.5 11.6,124.7 6.9,125.35 11.6,125.7 11.6,126.7 12.4,126.7 13.2,126.7 22,130.5 23,130.5 23,131.5 24,131.5 25,131.5 25.8,131.5 26.6,131.5 27.4,131.5 25.8,132.3 26.6,132.3 27.4,132.3 24,132.5 25,132.5 25,133.5 26,133.5 15.2,135.3 18.4,135.6 17.2,142.5 18.2,142.5 19.2,142.5 20.2,142.5 20.2,143.4 12,143.5 13,143.5 14,143.5 15,143.5 16,143.5 20.2,144.3
HSIO2_RX_n: M1.30 P1.31 TP69.1 | length 57.5
  Top Layer w0.161: M1.30@36.1,94.125 36.169,94.194 36.964,94.194 36.989,94.219 37.216,94.219 39.419,94.219 41.111,95.911 41.111,126.9 41.111,127.629 39.92,128.82 38.628,128.82 38.383,129.064 v1(38.364,129.064)
  Bottom Layer w0.161: P1.31@24.75,125.525 ccw(c24.582,125.693) 24.82,125.693 24.82,126.271 cw(c24.862,126.271) 24.832,126.301 ccw(c24.802,126.331) 24.845,126.331 24.845,127.255 TP69.1@24.6,127.5 24.6,127.519 24.844,127.764 24.844,128.079 25.585,128.82 25.98,128.82 38.119,128.82 v1(38.364,129.064)
HSIO2_RX_p: M1.28 P1.29 TP66.1 | length 57.5
  Top Layer w0.161: M1.28@36.1,94.625 36.169,94.555 36.964,94.555 36.989,94.53 37.345,94.53 39.291,94.53 40.8,96.04 40.8,127.5 39.791,128.509 38.628,128.509 38.383,128.264 v1(38.364,128.264)
  Bottom Layer w0.161: P1.29@25.25,125.525 cw(c25.418,125.693) 25.181,125.693 25.181,126.271 ccw(c25.138,126.271) 25.168,126.301 cw(c25.198,126.331) 25.156,126.331 25.156,127.256 TP66.1@25.4,127.5 25.4,127.519 25.155,127.764 25.155,127.951 25.714,128.509 26.1,128.509 26.542,128.509 cw(c26.542,128.328) 26.722,128.328 26.722,128.261 ccw(c26.903,128.261) 27.083,128.261 27.083,128.328 cw(c27.264,128.328) 27.444,128.328 27.444,128.261 ccw(c27.625,128.261) 27.805,128.261 27.805,128.328 cw(c27.986,128.328) 28.166,128.328 28.166,128.309 ccw(c28.347,128.309) 28.527,128.309 28.527,128.328 cw(c28.708,128.328) 28.708,128.509 29,128.509 38.119,128.509 v1(38.364,128.264)
HSIO2_TX_n: C4.2 M1.27 TP70.1 | length 3.8
  Top Layer w0.161: C4.2@24.425,95.4 24.458,95.367 24.833,95.367 TP70.1@25.4,94.8 25.492,94.8 25.661,94.969 27.029,94.969 27.054,94.944 27.732,94.944 cw(c27.732,94.707) M1.27@27.9,94.875
HSIO2_TX_p: C3.2 M1.25 TP68.1 | length 3.4
  Top Layer w0.161: C3.2@24.991,95.966 24.991,95.841 25.332,95.5 25.743,95.5 25.813,95.569 25.813,95.587 25.857,95.587 26.164,95.28 27.029,95.28 27.054,95.305 27.732,95.305 ccw(c27.732,95.543) M1.25@27.9,95.375
HSIO3_RX_n: M1.36 P1.43 TP75.1 | length 65.6
  Top Layer w0.161: M1.36@36.1,92.625 36.169,92.694 36.964,92.694 36.989,92.719 37.216,92.719 39.659,92.719 42.311,95.371 42.311,129.129 41.184,130.256 40.228,130.256 39.983,130.5 v1(39.964,130.5)
  Bottom Layer w0.161: P1.43@21.75,125.525 ccw(c21.582,125.693) 21.82,125.693 21.82,126.271 cw(c21.862,126.271) 21.832,126.301 ccw(c21.802,126.331) 21.845,126.331 21.845,127.764 22.654,128.573 22.654,128.854 TP75.1@22.7,128.9 22.746,128.946 23.027,128.946 24.091,130.011 36.494,130.011 ccw(c36.493,130.172) 36.505,130.011 39.614,130.248 39.694,130.254 cw(c39.719,129.944) 39.719,130.255 v1(39.964,130.5)
HSIO3_RX_p: M1.34 P1.41 TP72.1 | length 65.6
  Top Layer w0.161: M1.34@36.1,93.125 36.169,93.055 36.964,93.055 36.989,93.03 37.345,93.03 39.53,93.03 42,95.5 42,129 41.056,129.945 40.228,129.945 39.983,129.7 v1(39.964,129.7)
  Bottom Layer w0.161: P1.41@22.25,125.525 cw(c22.418,125.693) 22.181,125.693 22.181,126.271 ccw(c22.138,126.271) 22.168,126.301 cw(c22.198,126.331) 22.156,126.331 22.156,127.636 22.873,128.354 23.154,128.354 TP72.1@23.2,128.4 23.246,128.446 23.246,128.727 24.22,129.7 24.5,129.7 24.942,129.7 cw(c24.942,129.52) 25.122,129.52 25.122,129.456 ccw(c25.303,129.456) 25.483,129.456 25.483,129.52 cw(c25.664,129.52) 25.844,129.52 25.844,129.456 ccw(c26.025,129.456) 26.205,129.456 26.205,129.52 cw(c26.386,129.52) 26.566,129.52 26.566,129.492 ccw(c26.747,129.492) 26.927,129.492 26.927,129.52 cw(c27.108,129.52) 27.108,129.7 28.1,129.7 36.494,129.7 ccw(c36.494,130.011) 36.5,129.7 ccw(c36.493,130.172) 36.528,129.701 39.651,129.939 39.719,129.944 v1(39.964,129.7)
HSIO3_TX_n: C6.2 M1.33 TP76.1 | length 5.2
  Top Layer w0.161: C6.2@23.171,94.164 23.203,94.131 23.549,94.131 24.211,93.469 25.439,93.469 25.683,93.225 TP76.1@25.703,93.225 25.722,93.225 25.967,93.469 M1.33@27.195,93.469 ; M1.33@27.195,93.444 27.732,93.444 cw(c27.732,93.207) M1.33@27.9,93.375
HSIO3_TX_p: C5.2 M1.31 TP74.1 | length 5.2
  Top Layer w0.161: C5.2@23.736,94.729 23.769,94.697 23.769,94.351 24.339,93.78 24.475,93.78 24.556,93.78 24.65,93.875 24.65,93.94 24.722,94.012 24.939,94.012 25.011,93.94 25.011,93.875 25.105,93.78 25.375,93.78 25.439,93.78 25.683,94.025 25.747,94.025 25.967,93.805 27.732,93.805 ccw(c27.732,94.043) M1.31@27.9,93.875
HSIO6_RX_n: M1.66 P2.41 TP84.1 | length 48.8
  Top Layer w0.161: v1(33.155,93.015) 33.155,92.996 33.4,92.751 33.4,86.16 34.341,85.219 35.211,85.219 35.236,85.194 36.03,85.194 M1.66@36.1,85.125 ; P2.41@34.93,125.25 34.999,125.18 35.694,125.18 35.719,125.155 37.236,125.155 37.481,125.4 TP84.1@37.5,125.4 v1(38.1,125.4)
  Bottom Layer w0.161: v1(33.155,93.015) 33.155,93.034 33.4,93.279 33.4,93.84 34.104,94.544 35.374,94.544 35.9,95.07 35.9,107.14 36.8,108.04 36.8,124.435 37.521,125.156 37.836,125.156 38.081,125.4 v1(38.1,125.4)
HSIO6_RX_p: M1.64 P2.43 TP85.1 | length 48.8
  Top Layer w0.161: v1(33.955,93.015) 33.955,92.996 33.711,92.751 33.711,86.289 34,86 34.47,85.53 35.211,85.53 35.236,85.555 36.03,85.555 M1.64@36.1,85.625 ; P2.43@34.93,124.75 34.999,124.819 35.694,124.819 35.719,124.844 37.236,124.844 37.481,124.6 TP85.1@37.5,124.6 v1(38.1,124.6)
  Bottom Layer w0.161: v1(33.955,93.015) 33.955,93.034 33.711,93.279 33.711,93.711 34.233,94.233 35.503,94.233 36.211,94.941 36.211,107.011 37.111,107.911 37.111,122.075 37.111,122.517 cw(c37.292,122.517) 37.292,122.697 37.341,122.697 ccw(c37.341,122.878) 37.341,123.058 37.292,123.058 cw(c37.292,123.239) 37.292,123.419 37.341,123.419 ccw(c37.341,123.6) 37.341,123.78 37.292,123.78 cw(c37.292,123.961) 37.111,123.961 37.111,124.306 37.48,124.675 37.649,124.845 37.836,124.845 38.081,124.6 v1(38.1,124.6)
HSIO6_TX_n: C63.2 M1.63 TP80.1 | length 4.4
  Top Layer w0.161: C63.2@24,85.2 24.046,85.2 24.291,85.445 24.736,85.445 24.981,85.2 TP80.1@25,85.2 25.019,85.2 25.264,85.445 25.884,85.445 26.409,85.969 27.011,85.969 27.036,85.944 M1.63@27.831,85.944
HSIO6_TX_p: C64.2 M1.61 TP83.1 | length 4.4
  Top Layer w0.161: C64.2@24,86 24.046,86 24.291,85.756 24.736,85.756 24.981,86 TP83.1@25,86 25.019,86 25.264,85.756 25.756,85.756 26.28,86.28 27.011,86.28 27.036,86.305 M1.61@27.831,86.305
HSIO8_RX_n: C43.2 M1.42 TP26.1 | length 38.2
  Top Layer w0.161: M1.42@36.1,91.125 cw(c36.268,90.957) 36.268,91.194 36.946,91.194 ccw(c36.946,91.237) 36.976,91.207 cw(c37.006,91.177) 37.006,91.219 38.8,91.219 39.044,90.975 TP26.1@39.064,90.975 39.308,91.219 39.444,91.219 cw(c39.444,90.239) 39.747,91.172 cw(c39.444,90.239) 39.83,91.14 40.138,90.932 40.646,90.424 40.646,90.291 40.623,90.268 40.623,90.166 40.776,90.013 40.878,90.013 40.916,90.051 41.019,90.051 41.172,89.898 41.172,89.796 41.133,89.758 41.133,89.656 41.287,89.503 41.389,89.503 41.411,89.525 41.545,89.525 43.88,87.19 43.937,87.133 48.426,82.644 cw(c46.63,80.848) 49.17,80.848 49.17,68.754 49.17,61.49 48.925,61.246 C43.2@48.925,61.2
HSIO8_RX_p: C42.2 M1.40 TP25.1 | length 38.3
  Top Layer w0.161: M1.40@36.1,91.625 ccw(c36.268,91.793) 36.268,91.555 36.946,91.555 cw(c36.946,91.513) 36.976,91.543 ccw(c37.006,91.573) 37.006,91.53 38.8,91.53 TP25.1@39.044,91.775 39.064,91.775 39.308,91.53 39.446,91.53 cw(c39.446,90.243) 40.357,91.153 48.648,82.862 cw(c46.638,80.852) 49.481,80.852 49.481,68.883 49.481,61.49 49.725,61.246 C42.2@49.725,61.2
HSIO8_TX_n: C35.2 M1.39 TP14.1 | length 4.3
  Top Layer w0.161: C35.2@24,92 24.046,92 24.291,92.245 24.736,92.245 24.981,92 TP14.1@25,92 25.019,92 25.264,92.245 25.555,92.245 26.183,91.992 ccw(c26.3,92.28) 26.186,91.991 26.187,91.991 ccw(c26.3,92.28) 26.299,91.969 27.011,91.969 27.036,91.944 27.831,91.944 M1.39@27.9,91.875
HSIO8_TX_p: C34.2 M1.37 TP11.1 | length 4.3
  Top Layer w0.161: C34.2@24,92.8 24.046,92.8 24.291,92.556 24.736,92.556 24.981,92.8 TP11.1@25,92.8 25.019,92.8 25.264,92.556 25.556,92.556 cw(c25.555,92.4) 25.557,92.555 cw(c25.555,92.244) 25.673,92.533 26.3,92.28 27.011,92.28 27.036,92.305 27.831,92.305 M1.37@27.9,92.375
HSIO9_RX_n: C45.2 M1.48 TP28.1 | length 38.3
  Top Layer w0.161: M1.48@36.1,89.625 cw(c36.268,89.457) 36.268,89.694 36.946,89.694 ccw(c36.946,89.737) 36.976,89.707 cw(c37.006,89.677) 37.006,89.719 38.155,89.719 TP28.1@38.4,89.475 38.419,89.475 38.664,89.719 38.798,89.719 cw(c38.798,87.179) 39.823,89.504 cw(c38.798,87.179) 39.901,89.468 40.595,88.976 40.767,88.803 40.767,88.669 40.753,88.655 40.753,88.553 40.906,88.4 41.008,88.4 41.038,88.43 41.14,88.43 41.293,88.277 41.293,88.175 41.282,88.163 41.282,88.061 41.435,87.908 41.537,87.908 41.549,87.919 41.651,87.919 41.804,87.766 41.804,87.664 41.788,87.648 41.788,87.546 41.941,87.393 42.044,87.393 42.177,87.393 42.63,86.94 42.687,86.883 46.826,82.744 cw(c45.03,80.948) 47.57,80.948 47.57,59.29 47.325,59.046 C45.2@47.325,59
HSIO9_RX_p: C44.2 M1.46 TP27.1 | length 38.3
  Top Layer w0.161: M1.46@36.1,90.125 ccw(c36.268,90.293) 36.268,90.055 36.946,90.055 cw(c36.946,90.013) 36.976,90.043 ccw(c37.006,90.073) 37.006,90.03 38.156,90.03 TP27.1@38.4,90.275 38.419,90.275 38.664,90.03 38.802,90.03 cw(c38.802,87.188) 40.812,89.198 47.048,82.962 cw(c45.038,80.952) 47.881,80.952 47.881,59.29 48.125,59.046 C44.2@48.125,59
HSIO9_TX_n: C37.2 M1.45 TP20.1 | length 4.2
  Top Layer w0.161: C37.2@24,90.3 24.046,90.3 24.291,90.545 24.736,90.545 24.981,90.3 TP20.1@25,90.3 25.019,90.3 25.264,90.545 25.555,90.545 25.967,90.474 ccw(c26.02,90.78) 26.017,90.469 ; 26.02,90.469 27.011,90.469 27.036,90.444 27.831,90.444 M1.45@27.9,90.375
HSIO9_TX_p: C36.2 M1.43 TP19.1 | length 4.2
  Top Layer w0.161: C36.2@24,91.1 24.046,91.1 24.291,90.856 24.736,90.856 24.981,91.1 TP19.1@25,91.1 25.019,91.1 25.264,90.856 25.555,90.856 cw(c25.555,90.544) 25.609,90.851 26.02,90.78 27.011,90.78 27.036,90.805 27.831,90.805 M1.43@27.9,90.875
HSIO10_RX_n: C47.2 M1.54 TP30.1 | length 33.9
  Top Layer w0.161: M1.54@36.1,88.125 cw(c36.268,87.957) 36.268,88.194 36.946,88.194 ccw(c36.946,88.237) 36.976,88.207 cw(c37.006,88.177) 37.006,88.219 38.8,88.219 39.044,87.975 TP30.1@39.064,87.975 39.308,88.219 39.444,88.219 cw(c39.444,87.48) 39.967,88.003 40.279,87.691 40.279,87.558 40.271,87.55 40.271,87.448 40.425,87.295 40.527,87.295 40.55,87.318 40.652,87.318 40.805,87.165 40.805,87.063 40.789,87.046 40.789,86.944 40.942,86.791 41.044,86.791 41.06,86.807 41.163,86.807 41.316,86.654 41.316,86.552 41.3,86.537 41.3,86.434 41.453,86.281 41.555,86.281 41.689,86.281 41.78,86.19 45.201,82.77 cw(c43.404,80.973) 45.944,80.973 45.944,61.491 45.7,61.246 C47.2@45.7,61.2
HSIO10_RX_p: C46.2 M1.52 TP29.1 | length 33.9
  Top Layer w0.161: M1.52@36.1,88.625 ccw(c36.268,88.793) 36.268,88.555 36.946,88.555 cw(c36.946,88.513) 36.976,88.543 ccw(c37.006,88.573) 37.006,88.53 38.8,88.53 39.044,88.775 TP29.1@39.064,88.775 39.308,88.53 39.447,88.53 cw(c39.447,87.487) 40.185,88.225 45.423,82.987 cw(c43.413,80.977) 46.255,80.977 46.255,61.491 46.5,61.246 C46.2@46.5,61.2
HSIO10_TX_n: C39.2 M1.51 TP22.1 | length 4.3
  Top Layer w0.161: C39.2@24,88.6 24.046,88.6 24.291,88.845 24.736,88.845 24.981,88.6 TP22.1@25,88.6 25.019,88.6 25.264,88.845 25.6,88.844 ccw(c25.6,89.155) 25.601,88.844 ccw(c25.6,89.155) 25.65,88.849 26.4,88.969 27.011,88.969 27.036,88.944 27.831,88.944 M1.51@27.9,88.875
HSIO10_TX_p: C38.2 M1.49 TP21.1 | length 4.3
  Top Layer w0.161: C38.2@24,89.4 24.046,89.4 24.29,89.156 24.736,89.156 24.981,89.4 TP21.1@25,89.4 25.019,89.4 25.264,89.156 ; 25.265,89.155 25.6,89.155 26.349,89.276 cw(c26.4,88.969) 26.399,89.28 ; 26.4,89.28 27.011,89.28 27.036,89.305 27.831,89.305 M1.49@27.9,89.375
